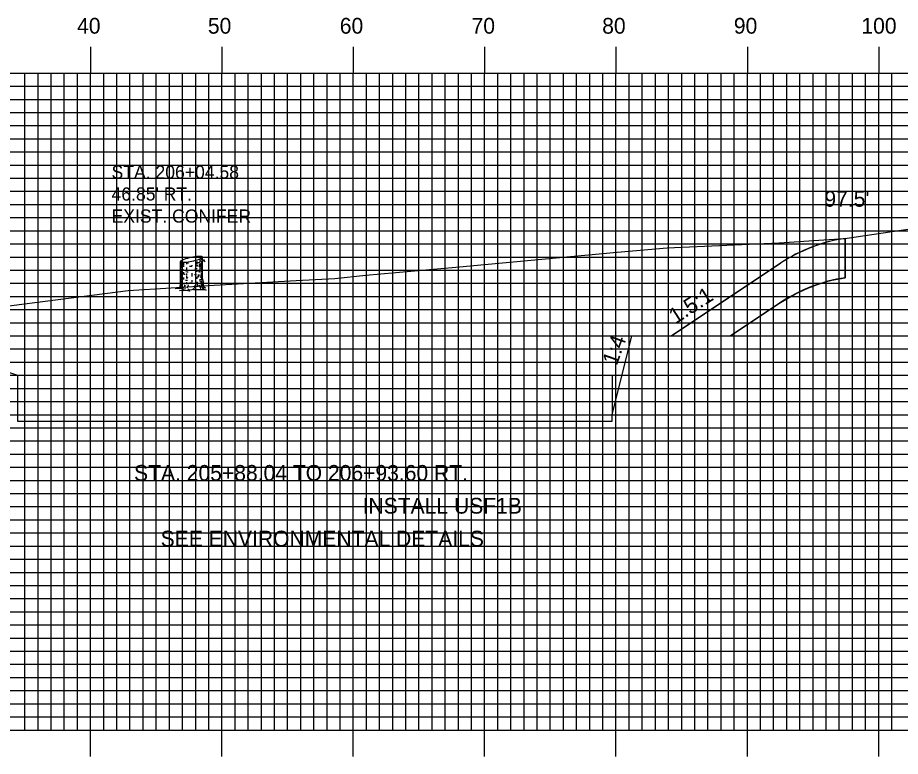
# Model space of a CAD drawing. Extents: x 1793272 to 1793615, y 442591 to 442811.
# Drawn here: x 1793472.2 to 1793539.4, y 442676.7 to 442732.9 of the extents above; entities that cross this region are included whole.
import ezdxf

# ---------------------------------------------------------------- set-up
doc = ezdxf.new("R2010")
doc.units = 0
for name, color, linetype in [('ANNOTATION', 7, 'Continuous'), ('D_Roadway_FinishedGrade', 7, 'Continuous'), ('D_Roadway_SlopeLines', 7, 'Continuous'), ('D_Text_Monospaced', 7, 'Continuous'), ('D_Text_Standard', 7, 'Continuous'), ('H_V ANNOTATION', 7, 'Continuous'), ('M_Trees_Conifer_Pay', 7, 'Continuous'), ('MAJOR', 7, 'Continuous'), ('MINOR', 7, 'Continuous'), ('S_Roadway_Centerline', 7, 'Continuous')]:
    doc.layers.add(name, color=color, linetype=linetype)

msp = doc.modelspace()

# ---------------------------------------------------------------- linework, layer by layer
at = {"layer": 'ANNOTATION'}
msp.add_lwpolyline([(1793520.128, 442708.665), (1793524.095, 442708.665)], dxfattribs=at)
msp.add_lwpolyline([(1793520.128, 442708.665), (1793524.095, 442708.665)], dxfattribs=at)
at = {"layer": 'D_Roadway_FinishedGrade'}
for p, q in [((1793535.238, 442716.083), (1793535.238, 442713.083)), ((1793472.251, 442705.665), (1793517.518, 442705.665)), ((1793517.518, 442705.665), (1793517.518, 442702.665))]:
    msp.add_line(p, q, dxfattribs=at)
for points in [[(1793522.022, 442708.665), (1793530.329, 442714.197)], [(1793530.329, 442711.197), (1793526.527, 442708.665)], [(1793467.975, 442707.104), (1793472.244, 442705.665), (1793472.244, 442702.165), (1793517.518, 442702.165), (1793517.518, 442702.665)]]:
    msp.add_lwpolyline(points, dxfattribs=at)
for centre in [(1793536.981, 442704.21), (1793536.981, 442701.21)]:
    msp.add_arc(centre, 12, 98.34941, 123.66488, dxfattribs=at)
at = {"layer": 'D_Roadway_SlopeLines'}
for p, q in [((1793517.518, 442702.665), (1793519.018, 442708.665)), ((1793519.018, 442708.665), (1793523.018, 442708.665))]:
    msp.add_line(p, q, dxfattribs=at)
msp.add_lwpolyline([(1793522.022, 442708.665), (1793526.527, 442708.665), (1793530.329, 442711.197), (1793531.476, 442711.873), (1793532.398, 442712.3), (1793533.133, 442712.576), (1793533.655, 442712.74), (1793534.241, 442712.893), (1793535.238, 442713.083), (1793535.238, 442716.083), (1793534.467, 442715.944), (1793533.58, 442715.718), (1793532.705, 442715.422), (1793531.56, 442714.916), (1793530.99, 442714.607), (1793530.329, 442714.197)], close=True, dxfattribs=at)
msp.add_lwpolyline([(1793524.095, 442708.665), (1793524.095, 442708.665), (1793526.527, 442708.665)], dxfattribs=at)
at = {"layer": 'M_Trees_Conifer_Pay'}
for p, q in [((1793486.125, 442714.523), (1793486.125, 442714.3)), ((1793486.243, 442714.584), (1793486.243, 442714.422)), ((1793486.314, 442713.01), (1793486.314, 442714.657)), ((1793484.65, 442712.599), (1793484.65, 442714.321)), ((1793484.698, 442714.284), (1793484.698, 442713.813)), ((1793484.756, 442714.273), (1793484.756, 442714.175)), ((1793484.756, 442714.101), (1793484.756, 442713.897)), ((1793484.756, 442713.839), (1793484.756, 442713.64)), ((1793484.881, 442714.265), (1793484.881, 442714.033)), ((1793484.881, 442713.992), (1793484.881, 442713.918)), ((1793485.101, 442714.285), (1793485.101, 442714.117)), ((1793485.101, 442713.88), (1793485.101, 442713.643)), ((1793485.507, 442714.054), (1793485.507, 442713.958)), ((1793485.897, 442714.327), (1793485.897, 442714.128)), ((1793485.897, 442714.07), (1793485.897, 442713.981)), ((1793486.125, 442714.212), (1793486.125, 442714.164)), ((1793486.125, 442713.829), (1793486.125, 442713.697)), ((1793486.182, 442714.029), (1793486.131, 442713.969)), ((1793486.243, 442714.354), (1793486.243, 442714.226)), ((1793486.243, 442714.039), (1793486.243, 442713.703)), ((1793484.698, 442713.748), (1793484.698, 442713.44)), ((1793484.698, 442713.393), (1793484.698, 442712.901)), ((1793484.756, 442713.592), (1793484.756, 442713.256)), ((1793484.756, 442713.203), (1793484.756, 442713.067)), ((1793484.881, 442713.514), (1793484.881, 442713.376)), ((1793484.881, 442713.104), (1793484.881, 442712.962)), ((1793485.101, 442713.399), (1793485.101, 442713.246)), ((1793485.101, 442713.203), (1793485.101, 442713.03)), ((1793485.507, 442713.44), (1793485.507, 442713.366)), ((1793485.507, 442713.341), (1793485.507, 442713.193)), ((1793485.897, 442713.634), (1793485.897, 442713.529)), ((1793485.897, 442713.162), (1793485.897, 442713.016)), ((1793486.125, 442713.586), (1793486.125, 442713.477)), ((1793486.125, 442713.341), (1793486.125, 442713.199)), ((1793486.243, 442713.666), (1793486.243, 442713.504)), ((1793486.243, 442713.456), (1793486.243, 442713.24)), ((1793486.243, 442713.209), (1793486.243, 442713.135)), ((1793486.243, 442713.094), (1793486.243, 442712.921)), ((1793484.698, 442712.847), (1793484.698, 442712.599)), ((1793484.756, 442712.968), (1793484.756, 442712.59)), ((1793484.881, 442712.701), (1793484.881, 442712.606)), ((1793485.101, 442712.752), (1793485.101, 442712.599)), ((1793485.507, 442712.901), (1793485.507, 442712.748)), ((1793485.897, 442712.783), (1793485.897, 442712.695)), ((1793486.125, 442712.972), (1793486.125, 442712.8)), ((1793484.881, 442712.206), (1793485.044, 442712.27)), ((1793485.318, 442712.142), (1793485.192, 442712.206))]:
    msp.add_line(p, q, dxfattribs=at)
for points in [[(1793486.131, 442714.155), (1793486.168, 442714.08), (1793486.215, 442714.138), (1793486.273, 442714.206), (1793486.366, 442714.399), (1793486.43, 442714.447), (1793486.461, 442714.453)], [(1793486.098, 442714.117), (1793486.067, 442714.033), (1793486.063, 442713.965), (1793486.094, 442713.901)], [(1793486.146, 442713.901), (1793486.182, 442714.029), (1793486.246, 442714.144), (1793486.277, 442714.212), (1793486.346, 442714.358)], [(1793486.36, 442714.388), (1793486.436, 442714.395), (1793486.508, 442714.296)], [(1793484.829, 442713.627), (1793484.824, 442713.722), (1793484.867, 442713.699), (1793484.867, 442713.605)], [(1793485.969, 442713.228), (1793485.981, 442713.151), (1793486.028, 442713.162), (1793486.016, 442713.328)], [(1793486.314, 442713.01), (1793486.366, 442712.748), (1793486.382, 442712.474), (1793486.44, 442712.349), (1793486.575, 442712.318), (1793486.345, 442712.281), (1793486.345, 442712.281), (1793486.351, 442712.233), (1793486.598, 442712.139), (1793486.324, 442712.155), (1793485.969, 442712.176), (1793485.647, 442712.165), (1793485.654, 442712.248), (1793485.505, 442712.165), (1793485.318, 442712.142), (1793485.343, 442712.075), (1793485.075, 442712.118), (1793484.854, 442712.091), (1793484.562, 442712.108), (1793484.85, 442712.165), (1793484.881, 442712.206), (1793484.719, 442712.264), (1793484.482, 442712.275), (1793484.241, 442712.275), (1793484.583, 442712.332), (1793484.624, 442712.412), (1793484.65, 442712.599)], [(1793484.698, 442712.552), (1793484.677, 442712.474), (1793484.657, 442712.38)], [(1793484.776, 442712.532), (1793484.782, 442712.416), (1793484.729, 442712.328), (1793484.719, 442712.264)], [(1793484.939, 442712.559), (1793484.939, 442712.427), (1793484.85, 442712.328)], [(1793485.165, 442712.318), (1793485.233, 442712.412), (1793485.26, 442712.552)], [(1793485.654, 442712.248), (1793485.728, 442712.39), (1793485.738, 442712.491)], [(1793485.904, 442712.617), (1793485.915, 442712.491), (1793485.989, 442712.447)], [(1793486.182, 442712.227), (1793486.168, 442712.365), (1793486.094, 442712.495)], [(1793486.141, 442712.722), (1793486.215, 442712.617), (1793486.22, 442712.443), (1793486.345, 442712.281)], [(1793486.24, 442712.867), (1793486.246, 442712.722), (1793486.293, 442712.653), (1793486.304, 442712.454)]]:
    msp.add_lwpolyline(points, dxfattribs=at)
for centre, radius, start, end in [((1793485.149, 442713.715), 0.802, 108.05939, 124.2194), ((1793486.506, 442709.554), 5.179, 101.7194, 108.05939), ((1793486.506, 442709.554), 5.179, 95.37941, 101.7194), ((1793484.459, 442719.424), 5.179, 281.7194, 288.05939), ((1793486.096, 442713.912), 0.802, 79.2194, 95.37941), ((1793485.816, 442715.262), 0.802, 288.05939, 304.2194), ((1793485.983, 442714.97), 0.571, 284.43166, 292.41325), ((1793486.199, 442714.453), 0.251, 71.05013, 79.2194), ((1793486.125, 442714.807), 0.251, 304.2194, 312.38868), ((1793486.183, 442714.625), 0.172, 300, 311.25059), ((1793486.254, 442714.613), 0.0817, 56.7194, 71.05013), ((1793486.239, 442714.682), 0.0817, 312.38868, 326.7194), ((1793486.255, 442714.542), 0.0624, 311.25059, 330), ((1793486.27, 442714.637), 0.0527, 46.92298, 56.7194), ((1793486.284, 442714.652), 0.0314, 34.2194, 46.92298), ((1793486.264, 442714.666), 0.0527, 326.7194, 336.51582), ((1793486.271, 442714.533), 0.0441, 330, 343.94846), ((1793486.288, 442714.655), 0.0264, 23.40735, 34.2194), ((1793486.283, 442714.658), 0.0314, 336.51582, 349.2194), ((1793486.292, 442714.657), 0.0226, 11.7194, 23.40735), ((1793486.281, 442714.53), 0.0334, 343.94846, 354.21506), ((1793486.292, 442714.657), 0.0226, 0.03145, 11.7194), ((1793486.288, 442714.657), 0.0264, 349.2194, 0.03145), ((1793484.682, 442714.143), 0.0334, 163.94846, 180), ((1793484.682, 442714.143), 0.0334, 180, 196.05154), ((1793484.677, 442714.321), 0.0264, 169.2194, 180.03145), ((1793484.673, 442714.321), 0.0226, 180.03145, 191.7194), ((1793484.693, 442714.146), 0.0441, 196.05154, 210), ((1793484.682, 442714.32), 0.0314, 156.51582, 169.2194), ((1793484.673, 442714.321), 0.0226, 191.7194, 203.40735), ((1793484.677, 442714.322), 0.0264, 203.40735, 214.2194), ((1793484.701, 442714.312), 0.0527, 146.7194, 156.51582), ((1793484.681, 442714.325), 0.0314, 214.2194, 226.92298), ((1793484.709, 442714.155), 0.0624, 210, 228.74941), ((1793484.726, 442714.296), 0.0817, 132.38868, 146.7194), ((1793484.695, 442714.341), 0.0527, 226.92298, 236.7194), ((1793484.711, 442714.365), 0.0817, 236.7194, 251.05013), ((1793484.781, 442714.238), 0.172, 228.74941, 240), ((1793484.839, 442714.171), 0.251, 124.2194, 132.38868), ((1793484.766, 442714.525), 0.251, 251.05013, 259.2194), ((1793484.98, 442714.583), 0.571, 240, 240.33672), ((1793484.982, 442714.372), 0.571, 240, 247.05866), ((1793484.869, 442715.066), 0.802, 259.2194, 275.37941), ((1793484.98, 442714.583), 0.571, 246.85973, 257.98457), ((1793484.459, 442719.424), 5.179, 275.37941, 281.7194), ((1793485.483, 442718.333), 4.124, 264.6955, 266.73309), ((1793485.481, 442718.1), 4.124, 268.07512, 270), ((1793485.481, 442718.1), 4.124, 270, 270.35814), ((1793485.482, 442717.889), 4.124, 273.70524, 275.95043), ((1793485.481, 442718.1), 4.124, 275.78493, 277.05584), ((1793485.483, 442718.333), 4.124, 276.23804, 278.1032), ((1793485.983, 442714.816), 0.571, 278.1032, 284.36665), ((1793485.983, 442714.372), 0.571, 284.44928, 297.04285), ((1793485.983, 442714.816), 0.571, 297.0237, 300), ((1793486.183, 442714.471), 0.172, 300, 311.25059), ((1793486.255, 442714.388), 0.0624, 311.25059, 330), ((1793486.271, 442714.379), 0.0441, 330, 343.94846), ((1793486.281, 442714.376), 0.0334, 343.94846, 354.21506), ((1793486.281, 442713.932), 0.0334, 343.94846, 354.21506), ((1793484.682, 442713.696), 0.0334, 163.94846, 180), ((1793484.682, 442713.696), 0.0334, 180, 196.05154), ((1793484.682, 442713.486), 0.0334, 163.94846, 180), ((1793484.682, 442713.486), 0.0334, 180, 196.05154), ((1793484.682, 442713.249), 0.0334, 163.94846, 180), ((1793484.682, 442713.249), 0.0334, 180, 196.05154), ((1793484.693, 442713.699), 0.0441, 196.05154, 210), ((1793484.693, 442713.489), 0.0441, 196.05154, 210), ((1793484.693, 442713.252), 0.0441, 196.05154, 210), ((1793484.709, 442713.708), 0.0624, 210, 228.74941), ((1793484.709, 442713.498), 0.0624, 210, 228.74941), ((1793484.709, 442713.262), 0.0624, 210, 228.74941), ((1793484.781, 442713.791), 0.172, 228.74941, 240), ((1793484.781, 442713.581), 0.172, 228.74941, 240), ((1793484.781, 442713.344), 0.172, 228.74941, 240), ((1793484.98, 442714.136), 0.571, 240, 240.33672), ((1793484.98, 442713.926), 0.571, 240, 246.85973), ((1793484.98, 442713.689), 0.571, 240, 246.85973), ((1793484.98, 442713.926), 0.571, 259.27072, 261.8968), ((1793485.481, 442717.444), 4.124, 261.8968, 263.14738), ((1793485.481, 442717.654), 4.124, 264.08098, 266.66759), ((1793485.481, 442717.207), 4.124, 264.71603, 266.31934), ((1793485.481, 442717.444), 4.124, 270, 270.35814), ((1793485.481, 442717.444), 4.124, 273.14934, 275.45691), ((1793485.481, 442717.654), 4.124, 277.61247, 278.1032), ((1793485.982, 442714.136), 0.571, 278.1032, 286.92962), ((1793485.982, 442713.689), 0.571, 285.39827, 297.18959), ((1793485.982, 442714.136), 0.571, 297.18959, 300), ((1793485.982, 442713.926), 0.571, 297.18959, 300), ((1793486.181, 442713.791), 0.172, 300, 311.25059), ((1793486.181, 442713.581), 0.172, 300, 311.25059), ((1793486.254, 442713.708), 0.0624, 311.25059, 330), ((1793486.254, 442713.498), 0.0624, 311.25059, 330), ((1793486.269, 442713.699), 0.0441, 330, 343.94846), ((1793486.269, 442713.489), 0.0441, 330, 343.94846), ((1793486.28, 442713.696), 0.0334, 343.94846, 354.21506), ((1793486.28, 442713.486), 0.0334, 343.94846, 354.21506), ((1793484.682, 442713.052), 0.0334, 163.94846, 180), ((1793484.682, 442712.856), 0.0334, 163.94846, 180), ((1793484.682, 442712.856), 0.0334, 180, 196.05154), ((1793484.682, 442712.636), 0.0334, 163.94846, 180), ((1793484.682, 442712.636), 0.0334, 180, 196.05154), ((1793484.693, 442712.859), 0.0441, 196.05154, 210), ((1793484.693, 442712.639), 0.0441, 196.05154, 210), ((1793484.709, 442712.868), 0.0624, 210, 228.74941), ((1793484.709, 442712.648), 0.0624, 210, 228.74941), ((1793484.781, 442712.951), 0.172, 228.74941, 240), ((1793484.781, 442712.731), 0.172, 228.74941, 240), ((1793484.97, 442713.498), 0.571, 241.23686, 248.02677), ((1793484.98, 442713.296), 0.571, 240, 246.85973), ((1793484.98, 442713.076), 0.571, 240, 244.53138), ((1793485.481, 442716.593), 4.124, 262.44379, 263.51202), ((1793485.481, 442717.009), 4.124, 263.49906, 265.83975), ((1793485.481, 442716.813), 4.124, 267.81166, 270), ((1793485.481, 442716.813), 4.124, 270, 270.13279), ((1793485.481, 442716.813), 4.124, 275.78493, 276.78961), ((1793485.481, 442716.593), 4.124, 277.36842, 278.1032), ((1793485.982, 442713.076), 0.571, 278.1032, 281.63703), ((1793485.982, 442713.296), 0.571, 288.50673, 297.27208), ((1793485.982, 442713.492), 0.571, 289.29072, 300), ((1793486.181, 442713.146), 0.172, 300, 311.25059), ((1793486.181, 442712.731), 0.172, 300, 311.25059), ((1793486.254, 442713.064), 0.0624, 311.25059, 330), ((1793486.254, 442712.648), 0.0624, 311.25059, 330), ((1793486.269, 442713.055), 0.0441, 330, 343.94846), ((1793486.269, 442712.639), 0.0441, 330, 343.94846), ((1793486.28, 442713.052), 0.0334, 343.94846, 354.21506), ((1793486.28, 442712.636), 0.0334, 343.94846, 354.21506)]:
    msp.add_arc(centre, radius, start, end, dxfattribs=at)
at = {"layer": 'MAJOR'}
for p, q in [((1793477.801, 442730.669), (1793477.801, 442728.665)), ((1793487.801, 442730.669), (1793487.801, 442728.665)), ((1793497.801, 442730.669), (1793497.801, 442728.665)), ((1793507.801, 442730.669), (1793507.801, 442728.665)), ((1793517.801, 442730.669), (1793517.801, 442728.665)), ((1793527.801, 442730.669), (1793527.801, 442728.665)), ((1793537.801, 442730.669), (1793537.801, 442728.665)), ((1793297.801, 442728.665), (1793577.801, 442728.665)), ((1793297.801, 442728.665), (1793577.801, 442728.665)), ((1793477.801, 442678.665), (1793477.801, 442728.665)), ((1793487.801, 442678.665), (1793487.801, 442728.665)), ((1793497.801, 442678.665), (1793497.801, 442728.665)), ((1793507.801, 442678.665), (1793507.801, 442728.665)), ((1793517.801, 442678.665), (1793517.801, 442728.665)), ((1793527.801, 442678.665), (1793527.801, 442728.665)), ((1793537.801, 442678.665), (1793537.801, 442728.665)), ((1793297.801, 442723.665), (1793577.801, 442723.665)), ((1793297.801, 442718.665), (1793577.801, 442718.665)), ((1793297.801, 442713.665), (1793577.801, 442713.665)), ((1793297.801, 442708.665), (1793577.801, 442708.665)), ((1793297.801, 442703.665), (1793577.801, 442703.665)), ((1793297.801, 442698.665), (1793577.801, 442698.665)), ((1793297.801, 442693.665), (1793577.801, 442693.665)), ((1793297.801, 442688.665), (1793577.801, 442688.665)), ((1793297.801, 442683.665), (1793577.801, 442683.665)), ((1793297.801, 442678.665), (1793577.801, 442678.665)), ((1793297.801, 442678.665), (1793577.801, 442678.665)), ((1793477.801, 442676.661), (1793477.801, 442678.665)), ((1793487.801, 442676.661), (1793487.801, 442678.665)), ((1793497.801, 442676.661), (1793497.801, 442678.665)), ((1793507.801, 442676.661), (1793507.801, 442678.665)), ((1793517.801, 442676.661), (1793517.801, 442678.665)), ((1793527.801, 442676.661), (1793527.801, 442678.665)), ((1793537.801, 442676.661), (1793537.801, 442678.665))]:
    msp.add_line(p, q, dxfattribs=at)
at = {"layer": 'MINOR'}
for p, q in [((1793472.801, 442678.665), (1793472.801, 442728.665)), ((1793473.801, 442678.665), (1793473.801, 442728.665)), ((1793474.801, 442678.665), (1793474.801, 442728.665)), ((1793475.801, 442678.665), (1793475.801, 442728.665)), ((1793476.801, 442678.665), (1793476.801, 442728.665)), ((1793478.801, 442678.665), (1793478.801, 442728.665)), ((1793479.801, 442678.665), (1793479.801, 442728.665)), ((1793480.801, 442678.665), (1793480.801, 442728.665)), ((1793481.801, 442678.665), (1793481.801, 442728.665)), ((1793482.801, 442678.665), (1793482.801, 442728.665)), ((1793483.801, 442678.665), (1793483.801, 442728.665)), ((1793484.801, 442678.665), (1793484.801, 442728.665)), ((1793485.801, 442678.665), (1793485.801, 442728.665)), ((1793486.801, 442678.665), (1793486.801, 442728.665)), ((1793488.801, 442678.665), (1793488.801, 442728.665)), ((1793489.801, 442678.665), (1793489.801, 442728.665)), ((1793490.801, 442678.665), (1793490.801, 442728.665)), ((1793491.801, 442678.665), (1793491.801, 442728.665)), ((1793492.801, 442678.665), (1793492.801, 442728.665)), ((1793493.801, 442678.665), (1793493.801, 442728.665)), ((1793494.801, 442678.665), (1793494.801, 442728.665)), ((1793495.801, 442678.665), (1793495.801, 442728.665)), ((1793496.801, 442678.665), (1793496.801, 442728.665)), ((1793498.801, 442678.665), (1793498.801, 442728.665)), ((1793499.801, 442678.665), (1793499.801, 442728.665)), ((1793500.801, 442678.665), (1793500.801, 442728.665)), ((1793501.801, 442678.665), (1793501.801, 442728.665)), ((1793502.801, 442678.665), (1793502.801, 442728.665)), ((1793503.801, 442678.665), (1793503.801, 442728.665)), ((1793504.801, 442678.665), (1793504.801, 442728.665)), ((1793505.801, 442678.665), (1793505.801, 442728.665)), ((1793506.801, 442678.665), (1793506.801, 442728.665)), ((1793508.801, 442678.665), (1793508.801, 442728.665)), ((1793509.801, 442678.665), (1793509.801, 442728.665)), ((1793510.801, 442678.665), (1793510.801, 442728.665)), ((1793511.801, 442678.665), (1793511.801, 442728.665)), ((1793512.801, 442678.665), (1793512.801, 442728.665)), ((1793513.801, 442678.665), (1793513.801, 442728.665)), ((1793514.801, 442678.665), (1793514.801, 442728.665)), ((1793515.801, 442678.665), (1793515.801, 442728.665)), ((1793516.801, 442678.665), (1793516.801, 442728.665)), ((1793518.801, 442678.665), (1793518.801, 442728.665)), ((1793519.801, 442678.665), (1793519.801, 442728.665)), ((1793520.801, 442678.665), (1793520.801, 442728.665)), ((1793521.801, 442678.665), (1793521.801, 442728.665)), ((1793522.801, 442678.665), (1793522.801, 442728.665)), ((1793523.801, 442678.665), (1793523.801, 442728.665)), ((1793524.801, 442678.665), (1793524.801, 442728.665)), ((1793525.801, 442678.665), (1793525.801, 442728.665)), ((1793526.801, 442678.665), (1793526.801, 442728.665)), ((1793528.801, 442678.665), (1793528.801, 442728.665)), ((1793529.801, 442678.665), (1793529.801, 442728.665)), ((1793530.801, 442678.665), (1793530.801, 442728.665)), ((1793531.801, 442678.665), (1793531.801, 442728.665)), ((1793532.801, 442678.665), (1793532.801, 442728.665)), ((1793533.801, 442678.665), (1793533.801, 442728.665)), ((1793534.801, 442678.665), (1793534.801, 442728.665)), ((1793535.801, 442678.665), (1793535.801, 442728.665)), ((1793536.801, 442678.665), (1793536.801, 442728.665)), ((1793538.801, 442678.665), (1793538.801, 442728.665)), ((1793297.801, 442727.665), (1793577.801, 442727.665)), ((1793297.801, 442726.665), (1793577.801, 442726.665)), ((1793297.801, 442725.665), (1793577.801, 442725.665)), ((1793297.801, 442724.665), (1793577.801, 442724.665)), ((1793297.801, 442722.665), (1793577.801, 442722.665)), ((1793297.801, 442721.665), (1793577.801, 442721.665)), ((1793297.801, 442720.665), (1793577.801, 442720.665)), ((1793297.801, 442719.665), (1793577.801, 442719.665)), ((1793297.801, 442717.665), (1793577.801, 442717.665)), ((1793297.801, 442716.665), (1793577.801, 442716.665)), ((1793297.801, 442715.665), (1793577.801, 442715.665)), ((1793297.801, 442714.665), (1793577.801, 442714.665)), ((1793297.801, 442712.665), (1793577.801, 442712.665)), ((1793297.801, 442711.665), (1793577.801, 442711.665)), ((1793297.801, 442710.665), (1793577.801, 442710.665)), ((1793297.801, 442709.665), (1793577.801, 442709.665)), ((1793297.801, 442707.665), (1793577.801, 442707.665)), ((1793297.801, 442706.665), (1793577.801, 442706.665)), ((1793297.801, 442705.665), (1793577.801, 442705.665)), ((1793297.801, 442704.665), (1793577.801, 442704.665)), ((1793297.801, 442702.665), (1793577.801, 442702.665)), ((1793297.801, 442701.665), (1793577.801, 442701.665)), ((1793297.801, 442700.665), (1793577.801, 442700.665)), ((1793297.801, 442699.665), (1793577.801, 442699.665)), ((1793297.801, 442697.665), (1793577.801, 442697.665)), ((1793297.801, 442696.665), (1793577.801, 442696.665)), ((1793297.801, 442695.665), (1793577.801, 442695.665)), ((1793297.801, 442694.665), (1793577.801, 442694.665)), ((1793297.801, 442692.665), (1793577.801, 442692.665)), ((1793297.801, 442691.665), (1793577.801, 442691.665)), ((1793297.801, 442690.665), (1793577.801, 442690.665)), ((1793297.801, 442689.665), (1793577.801, 442689.665)), ((1793297.801, 442687.665), (1793577.801, 442687.665)), ((1793297.801, 442686.665), (1793577.801, 442686.665)), ((1793297.801, 442685.665), (1793577.801, 442685.665)), ((1793297.801, 442684.665), (1793577.801, 442684.665)), ((1793297.801, 442682.665), (1793577.801, 442682.665)), ((1793297.801, 442681.665), (1793577.801, 442681.665)), ((1793297.801, 442680.665), (1793577.801, 442680.665)), ((1793297.801, 442679.665), (1793577.801, 442679.665))]:
    msp.add_line(p, q, dxfattribs=at)
at = {"layer": 'S_Roadway_Centerline'}
msp.add_lwpolyline([(1793465.628, 442710.201), (1793480.673, 442712.114), (1793487.2, 442712.516), (1793493.44, 442712.872), (1793496.384, 442713.039), (1793498.76, 442713.276), (1793505.616, 442713.896), (1793517.889, 442715.037), (1793521.699, 442715.364), (1793530.229, 442715.755), (1793533.615, 442715.963), (1793535.23, 442716.082), (1793546.032, 442717.667)], dxfattribs=at)

# ---------------------------------------------------------------- texts
at = {"layer": 'ANNOTATION'}
for s, height, rotation, p in [('64.9%', 0.01, 32.98345, (1793536.781, 442716.304)), ('64.9%', 0.01, 32.98345, (1793536.781, 442716.304)), ('1.5:1', 1.2, 32.76285, (1793522.32, 442709.526)), ('1:4', 1.2, 70.51601, (1793517.861, 442706.348)), ('1:4', 1.2, 70.51601, (1793517.861, 442706.348))]:
    msp.add_text(s, height=height, rotation=rotation, dxfattribs=at).set_placement(p)
at = {"layer": 'D_Text_Monospaced'}
for s, height, p in [('STA. 206+04.58', 0.99996, (1793479.397, 442720.631)), ("46.85' RT.", 1, (1793479.397, 442718.963)), ('EXIST. CONIFER', 0.99996, (1793479.397, 442717.283))]:
    msp.add_text(s, height=height, dxfattribs=at).set_placement(p)
at = {"layer": 'D_Text_Standard'}
for s, p in [("97.5'", (1793533.667, 442718.495)), ('STA. 205+88.04 TO 206+93.60 RT.', (1793481.11, 442697.634)), ('INSTALL USF1B', (1793498.508, 442695.134)), ('SEE ENVIRONMENTAL DETAILS', (1793483.135, 442692.634))]:
    msp.add_text(s, height=1.2, dxfattribs=at).set_placement(p)
at = {"layer": 'H_V ANNOTATION'}
for s, p in [('40', (1793476.773, 442731.665)), ('50', (1793486.73, 442731.665)), ('60', (1793496.773, 442731.665)), ('70', (1793506.805, 442731.665)), ('80', (1793516.751, 442731.665)), ('90', (1793526.773, 442731.665)), ('100', (1793536.484, 442731.665))]:
    msp.add_text(s, height=1.2, dxfattribs=at).set_placement(p)

doc.saveas('drawing.dxf')
